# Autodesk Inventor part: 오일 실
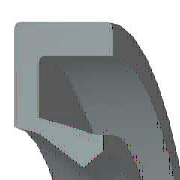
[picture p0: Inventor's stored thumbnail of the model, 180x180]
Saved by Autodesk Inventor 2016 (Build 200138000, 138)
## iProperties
IsCustomPart: 1
Created: 2012-02
Part Number: 오일 실
Material: 고무
Description: 오일 실 - 스프링 장착, 비스프링, 고무 덮개 G
Document SubType Name: Modeling
Standard: JIS B 2402
Designer: mduedu
Standards Organization: JIS
Language: ko-KR
Size Designation: 20 32 5 A
Categories: <MemberInstance><Categories><Category DisplayName="샤프트 부품" InternalName="7f7aeb1f-a693-4053-b835-cee3144e0d98" Mnemonic="SHFT"><Category DisplayName="실링" Intern
Density: 0.93 g/cm^3
Appearance: 고무 - 검은색 - 버전 1.1
Author: mduedu
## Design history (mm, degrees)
body "Solid1"
revolve "회전1" stored, may be unused: angle "d29" = 360 deg
chamfer "모따기1" distance "d30" = 0.25 (= 0.05 x b); stored, may be unused: second distance "d31" = 0.5 (= 0.1 x b), angle "d39" = 45 deg
chamfer "모따기2" distance "d32" = 0.5 (= 0.1 x b); stored, may be unused: second distance "d33" = 0.25 (= 0.05 x b), angle "d40" = 45 deg
fillet "모깎기1" dims "d34" = 0.25 (= 0.05 x b)
sketch "스케치2"
  geometry: L1 (10.997, -3.438)-(11.297, -5); L2 (10.597, -3.282)-(10.997, -3.438); L3 (10, -1.72)-(10.597, -3.282); L4 (11.091, -1.22)-(10, -1.72); L5 (12.133, -3.75)-(11.091, -1.22); L6 (13.333, -3.75)-(12.133, -3.75); L7 (14.667, -1.25)-(13.333, -3.75); L8 (14.667, 0)-(14.667, -1.25); L9 (16, 0)-(14.667, 0); L10 (16, -5)-(16, 0); L11 (11.297, -5)-(16, -5); L12 (0, -9.6)-(0, 1.6) reference; L13 (28, 0)-(14, 0) reference
  constraints: 22 end point, 3 horizontal, 2 vertical
  dimensions: "d2" = 5 distance of L10.start L9.start (= b); "d4" = 1.25 vertical distance of L5.start L1.end (= 0.25 x b); "d6" = 1.33333 distance of L9.start L8.start (= 0.111111 x dd - 0.111111 x Diam); "d8" = 1.25 distance of L8.start L7.start (= 0.25 x b); "d10" = 1.33333 horizontal distance of L7.start L6.start (= 0.111111 x dd - 0.111111 x Diam); "d12" = 1.21951 vertical distance of L9.start L4.start (= 0.243902 x b); "d14" = 1.09091 horizontal distance of L4.start L3.start (= 0.0909091 x dd - 0.0909091 x Diam); "d16" = 0.5 vertical distance of L4.start L3.start (= 0.1 x b); "d18" = 1.2 distance of L6.start L5.start (= 0.1 x dd - 0.1 x Diam); "d20" = 1.5625 vertical distance of L3.start L2.start (= 0.3125 x b); "d22" = 0.59701 horizontal distance of L3.start L2.start (= 0.0497512 x dd - 0.0497512 x Diam); "d24" = 0.3 horizontal distance of L1.start L1.end (= 0.025 x dd - 0.025 x Diam); "d26" = 1.5625 vertical distance of L1.start L1.end (= 0.3125 x b); "d28" = 0.4 horizontal distance of L2.start L1.start (= 0.0333333 x dd - 0.0333333 x Diam); "d35" = 0 distance between parallel lines of L13 L9; "d36" = 16 distance between parallel lines of L12 L10 (= 0.5 x dd); "d37" = 10 distance from line of L12 L3.start (= 0.5 x Diam)
other parameters: "dd" = 32 [user parameter; used in 8 equation terms], "b" = 5 [user parameter; used in 12 equation terms], "d1" = 8 (derived), "d3" = 2 (derived), "d5" = 2.22222 (derived), "d7" = 2 (derived), "d9" = 2.22222 (derived), "d11" = 1.95122 (derived), "d13" = 1.81818 (derived), "d15" = 0.8 (derived), "d17" = 2 (derived), "d19" = 2.5 (derived), "d21" = 0.99502 (derived), "d23" = 0.5 (derived), "d25" = 2.5 (derived), "d27" = 0.66667 (derived), "d38" = 0
